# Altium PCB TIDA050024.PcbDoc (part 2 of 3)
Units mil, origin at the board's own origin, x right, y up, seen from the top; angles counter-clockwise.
Board outline 5500.19 x 3301.39 mil, 4 copper layers (Top Layer, Signal Layer 1, Signal Layer 2, Bottom Layer), stack 46.8 mil thick; 153 components, 88 nets, 368 pads, 374 vias.
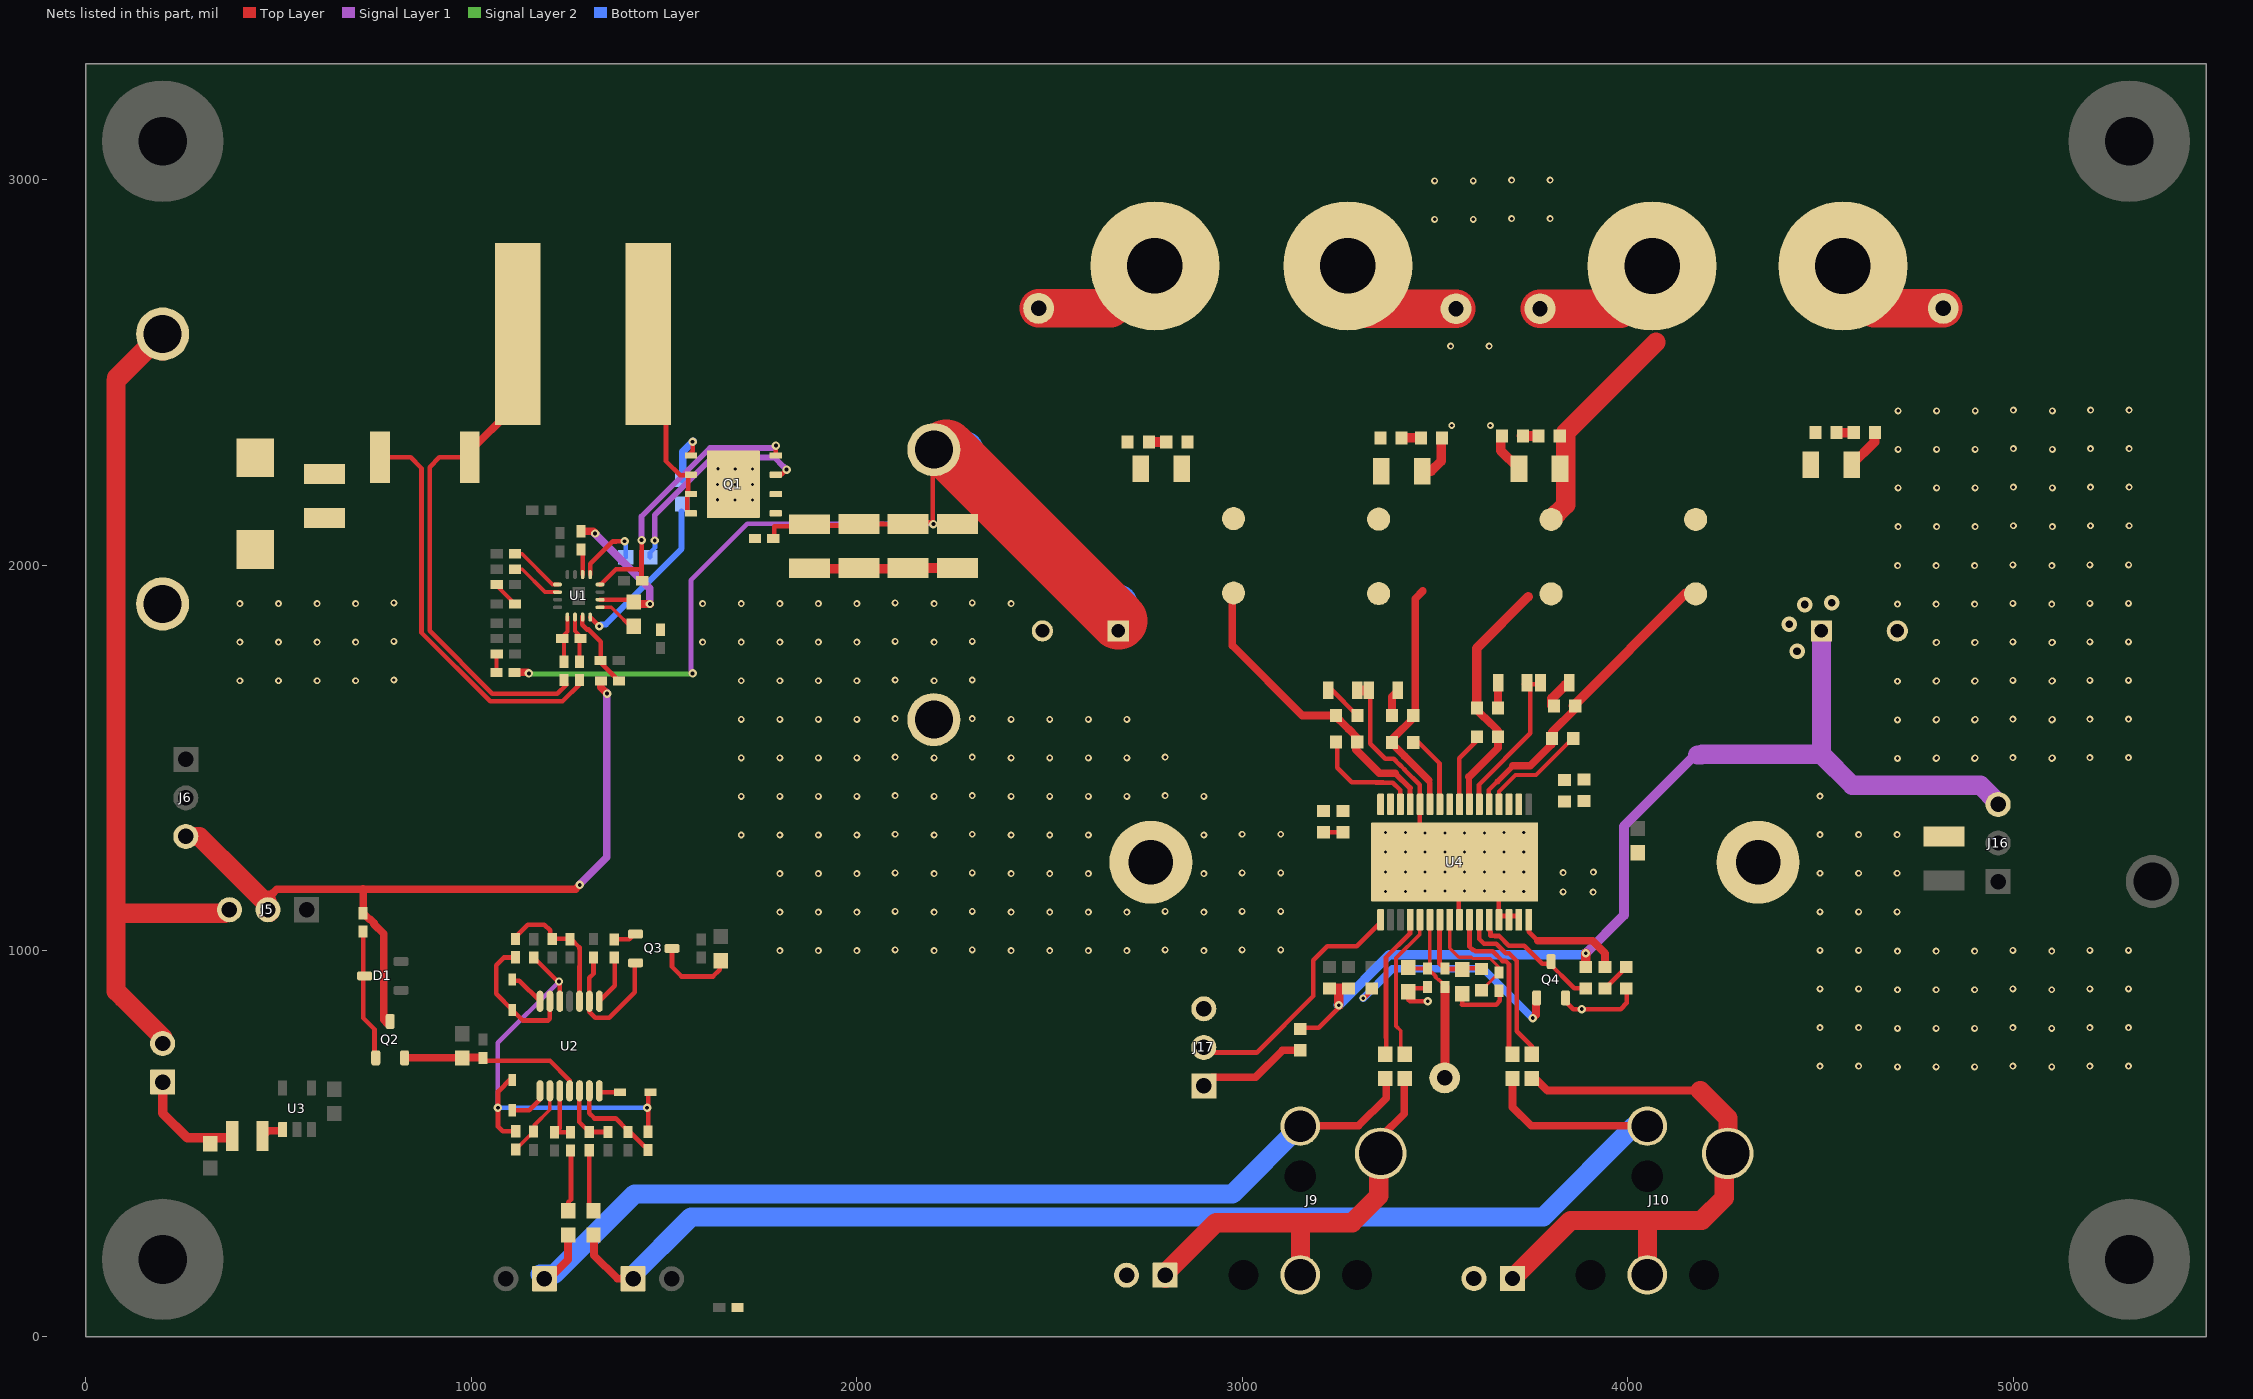
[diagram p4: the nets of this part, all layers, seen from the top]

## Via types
v1: diameter 18, hole 9, Top Layer to Bottom Layer, 291 vias
v2: diameter 22, hole 10, Top Layer to Bottom Layer, 26 vias
v3: diameter 19.68, hole 7.87, Top Layer to Bottom Layer, 18 vias
v4: diameter 19.68, hole 7.87, Top Layer to Bottom Layer, tented both sides, 16 vias
v5: diameter 18, hole 8, Top Layer to Bottom Layer, 9 vias
v6: diameter 40, hole 20, Top Layer to Bottom Layer, 6 vias
v7: diameter 24, hole 12, Top Layer to Bottom Layer, 5 vias
v8: diameter 20, hole 10, Top Layer to Bottom Layer, 2 vias
v9: diameter 30, hole 15, Top Layer to Bottom Layer, 1 vias

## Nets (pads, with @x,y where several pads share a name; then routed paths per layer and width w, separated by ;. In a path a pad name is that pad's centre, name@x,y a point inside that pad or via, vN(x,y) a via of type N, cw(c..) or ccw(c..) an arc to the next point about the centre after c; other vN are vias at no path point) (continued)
GND: C1.2 C2.2 C5.2 C6.2 C7.2 C8.2 C9.2 C17.2 C25.2 C27.2 C29.1 C30.1 C32.2 C39.2 C42.1 C43.1 C44.2 C46.2 C51.2 C53.2 C54.2 C55.1 C56.1 H1.1@4337.4,1230 H1.2 J2.1 J4.1 J17.3 JP1.2 JP2.2 Q1.9 Q4.2 R27.1@3480.57,906.95 R28.1 R33.1 R34.1 R35.1 R36.1 R39.1 R40.1 R41.1 R42.1 Rg1.2 Rg2.2 U1.9 U4.9 U4.13 U4.14 U4.15 U4.22 U4.25 U4.28 U4.33@3550.57,1230.57 | length 2518.7
  Top Layer w10: U1.9@1334.28,1891.31 1363.22,1891.31 C17.2@1425.03,1829.5
  Top Layer w12: J2.1@200,1950 J2.1@239.31,1950 ; C7.2@2000.71,1990.96 C7.2@2000.71,1998.84 ; C55.1@3210.57,1308.01 3259.88,1308.01 C56.1@3260.66,1308.79 ; R34.1@3314.8,1677.27 3331.52,1677.27 3331.52,1537.28 3370.58,1498.23 3392.56,1498.23 3406.22,1484.57 3406.35,1484.57 3420.41,1470.51 3420.41,1470.38 3460.18,1430.61 U4.28@3460.18,1389.88 ; U4.33@3460.16,1329.86 U4.28@3460.16,1386.09 ; R27.1@3479.4,903.4 3479.01,903.01 3430.57,903.01 3430.57,873.67 3434.63,869.61 v2(3480.67,869.61) ; U4.33@3481.22,1308.79 3482.72,1308.79 U4.33@3483.49,1309.56 ; U4.33@3536.23,1300.8 U4.33@3536.95,1301.52 ; U4.33@3561.5,1142.57 3561.5,1090.71 U4.9@3563.88,1088.33 ; 3569.63,860.55 3569.95,860.87 ; C43.1@3570.57,903.01 3570.57,861.48 3569.95,860.87 ; U4.22@3616.95,1362.32 3613.72,1362.32 3613.72,1431.43 3747.04,1564.75 R35.1@3747.04,1691.44 ; U4.33@3664.41,1144.48 3664.41,1091.16 3663.9,1090.66 U4.15@3716.08,1090.66 ; R28.1@3667.92,905.02 3667.92,870.86 3657.93,860.87 3569.95,860.87 ; R35.1@3729.76,1692.08 3761.32,1692.08 R36.1@3763.24,1694 ; Q4.2@3838.19,880.03 3838.19,874.94 3835.22,871.97 3857.99,849.2 v2(3880.17,849.2) ; v2(3880.17,849.2) 3980.83,849.24 3996.8,865.21 C46.2@3996.8,900.6 ; C27.2@4021.45,1260.32 C27.2@4024,1257.77
  Top Layer w25: C6.2@1872.99,1988.19 1875.76,1990.96 2000.71,1990.96 2122.16,1990.96 2126.31,1995.11 2128.33,1993.09 C9.2@2260.76,1993.09 ; R33.1@3298.17,1675.9 3298.49,1675.57 R34.1@3328.17,1675.57 ; C32.2@3466.58,2244.29 3489.62,2244.29 3515.78,2270.46 R40.1@3515.78,2327.98 ; R41.1@3673.15,2337.81 3669.93,2334.59 3669.93,2297.86 3717.21,2250.57 C39.2@3717.42,2250.57 ; C44.2@4580.3,2260.95 4639.42,2320.07 R42.1@4639.42,2345.02
  other v1: 4698.97,699.5 4798.97,699.5 4898.97,699.5 5098.97,699.5 4497.99,701.49 4597.99,701.49 4997.99,701.49 5197.99,701.49 5297.99,701.49 4698.97,799.5 4798.97,799.5 4898.97,799.5 5098.97,799.5 4497.99,801.49 4597.99,801.49 4997.99,801.49 5197.99,801.49 5297.99,801.49 4698.97,899.5 4798.97,899.5 4898.97,899.5 5098.97,899.5 4497.99,901.49 4597.99,901.49 4997.99,901.49 5197.99,901.49 5297.99,901.49 4698.97,999.5 4798.97,999.5 4898.97,999.5 5098.97,999.5 1800.45,1000.73 1900.45,1000.73 2000.45,1000.73 2200.45,1000.73 2400.45,1000.73 2500.45,1000.73 2600.45,1000.73 2700.45,1000.73 2900.45,1000.73 4497.99,1001.49 4597.99,1001.49 4997.99,1001.49 5197.99,1001.49 5297.99,1001.49 2099.47,1002.72 2299.47,1002.72 2799.47,1002.72 2999.47,1002.72 3099.47,1002.72 1800.45,1100.73 1900.45,1100.73 2000.45,1100.73 2200.45,1100.73 2400.45,1100.73 2500.45,1100.73 2600.45,1100.73 2700.45,1100.73 2900.45,1100.73 4497.99,1101.49 4597.99,1101.49 4697.99,1101.49 2099.47,1102.72 2299.47,1102.72 2799.47,1102.72 2999.47,1102.72 3099.47,1102.72 3832.05,1153.49 3909.58,1152.56 1800.45,1200.73 1900.45,1200.73 2000.45,1200.73 2200.45,1200.73 2400.45,1200.73 2500.45,1200.73 2600.45,1200.73 2900.45,1200.73 4497.99,1201.49 4597.99,1201.49 4697.99,1201.49 2099.47,1202.72 2299.47,1202.72 2999.47,1202.72 3099.47,1202.72 3831.95,1203.31 3910.53,1204.48 1700.45,1300.73 1800.45,1300.73 1900.45,1300.73 2000.45,1300.73 2200.45,1300.73 2400.45,1300.73 2500.45,1300.73 2600.45,1300.73 2900.45,1300.73 4497.99,1301.49 4597.99,1301.49 4697.99,1301.49 2099.47,1302.72 2299.47,1302.72 2999.47,1302.72 3099.47,1302.72 1700.45,1400.73 1800.45,1400.73 1900.45,1400.73 2000.45,1400.73 2200.45,1400.73 2400.45,1400.73 2500.45,1400.73 2600.45,1400.73 2700.45,1400.73 2900.45,1400.73 4497.99,1401.49 2099.47,1402.72 2299.47,1402.72 2799.47,1402.72 4698.97,1499.5 4798.97,1499.5 4898.97,1499.5 5098.97,1499.5 1700.45,1500.73 1800.45,1500.73 1900.45,1500.73 2000.45,1500.73 2200.45,1500.73 2400.45,1500.73 2500.45,1500.73 2600.45,1500.73 2700.45,1500.73 4800.45,1500.73 4900.45,1500.73 4997.99,1501.49 5100.45,1500.73 5197.99,1501.49 5297.99,1501.49 2099.47,1502.72 2299.47,1502.72 2799.47,1502.72 4698.97,1599.5 4798.97,1599.5 4898.97,1599.5 5098.97,1599.5 1700.45,1600.73 1800.45,1600.73 1900.45,1600.73 2000.45,1600.73 2400.45,1600.73 2500.45,1600.73 2600.45,1600.73 2700.45,1600.73 4800.57,1600.57 4900.57,1600.57 4997.99,1601.49 5100.57,1600.57 5197.99,1601.49 5297.99,1601.49 2099.47,1602.72 2299.47,1602.72 4698.97,1699.5 4798.97,1699.5 4898.97,1699.5 5098.97,1699.5 400.45,1700.73 500.45,1700.73 600.45,1700.73 700.45,1700.73 1700.45,1700.73 1800.45,1700.73 1900.45,1700.73 2000.45,1700.73 2200.45,1700.73 4800.45,1700.73 4900.45,1700.73 4997.99,1701.49 5100.45,1700.73 5197.99,1701.49 5297.99,1701.49 799.47,1702.72 2099.47,1702.72 2299.47,1702.72 4798.97,1799.5 4898.97,1799.5 5098.97,1799.5 400.45,1800.73 500.45,1800.73 600.45,1800.73 700.45,1800.73 1600.45,1800.73 1700.45,1800.73 1800.45,1800.73 1900.45,1800.73 2000.45,1800.73 2200.45,1800.73 4800.57,1800.57 4900.57,1800.57 4997.99,1801.49 5100.57,1800.57 5197.99,1801.49 5297.99,1801.49 799.47,1802.72 2099.47,1802.72 2299.47,1802.72 4698.97,1899.5 4798.97,1899.5 4898.97,1899.5 5098.97,1899.5 400.45,1900.73 500.45,1900.73 600.45,1900.73 700.45,1900.73 1600.45,1900.73 1700.45,1900.73 1800.45,1900.73 1900.45,1900.73 2000.45,1900.73 2200.45,1900.73 2400.45,1900.73 4997.99,1901.49 5197.99,1901.49 5297.99,1901.49 799.47,1902.72 2099.47,1902.72 2299.47,1902.72 4699.09,1999.34 4799.09,1999.34 4899.09,1999.34 5099.09,1999.34 4998.1,2001.33 5198.1,2001.33 5298.1,2001.33 4700.45,2100.73 4800.45,2100.73 4900.45,2100.73 5100.45,2100.73 4999.47,2102.72 5199.47,2102.72 5299.47,2102.72 4700.45,2200.73 4800.45,2200.73 4900.45,2200.73 5100.45,2200.73 4999.47,2202.72 5199.47,2202.72 5299.47,2202.72 4700.45,2300.73 4800.45,2300.73 4900.45,2300.73 5100.45,2300.73 4999.47,2302.72 5199.47,2302.72 5299.47,2302.72 3542.99,2362.72 3642.99,2362.72 4700.57,2400.57 4800.57,2400.57 4900.57,2400.57 5100.57,2400.57 4999.58,2402.56 5199.58,2402.56 5299.58,2402.56 3539.98,2568.29 3639.98,2568.29 3498.67,2897.45 3598.67,2897.45 3698.09,2899.06 3798.09,2899.06 3498.79,2997.3 3598.79,2997.3 3698.21,2998.9 3798.21,2998.9
  other v3: 3473.8,1155.77 3524.98,1155.77 3576.16,1155.77 3627.34,1155.77 3473.8,1204.98 3524.98,1204.98 3576.16,1204.98 3627.34,1204.98 3473.8,1256.16 3524.98,1256.16 3576.16,1256.16 3627.34,1256.16 3473.8,1305.37 3524.98,1305.37 3576.16,1305.37 3627.34,1305.37
  other v4: 3371.44,1153.8 3422.62,1153.8 3678.52,1153.8 3729.71,1153.8 3371.44,1204.98 3422.62,1204.98 3678.52,1204.98 3729.71,1204.98 3371.44,1256.16 3422.62,1256.16 3678.52,1256.16 3729.71,1256.16 3371.44,1307.34 3422.62,1307.34 3678.52,1307.34 3729.71,1307.34
  other v5: 1639.25,2170.19 1684.3,2169.73 1729.3,2169.73 1639.25,2210.19 1684.3,2209.73 1729.3,2209.73 1684.96,2250.16 1729.96,2250.16 1639.91,2250.62
GVDD: C43.2 R43.2 R44.1 U4.7 | length 236.8
  Top Layer w12: U4.7@3511.36,1090.66 3511.36,967.28 3525.23,953.4 3570.03,953.4 3572.28,955.65 R44.1@3618.04,955.65
HDRV: R11.1 U1.13 | length 195.3
  Top Layer w12: U1.13@1308.69,1975.96 1308.69,2004.49 1365.54,2061.34 1376.63,2061.34 ; 1367.02,2062.08 1370.35,2062.08 1370.72,2062.45 v2(1398.07,2062.45)
  Bottom Layer w12: v2@1397.94,2063.83 1400.87,2060.9 R11.1@1400.87,2021.02
HDRV1: Q1.3 R11.2 | length 560.2
  Top Layer w12: Q1.3@1790.04,2235 1804.57,2235 1818.06,2248.49 1818.06,2248.69 v2@1817.68,2249.08
  Signal Layer 1 w12: 1810.08,2256.03 1811.72,2256.03 1811.72,2253.98 v2@1810.49,2252.75
  Signal Layer 1 w15: v2(1476.07,2064.49) 1476.07,2130.41 1625.05,2279.38 1786.72,2279.38 1810.08,2256.03
  Bottom Layer w12: R11.2@1463.86,2021.02 1463.86,2032.96 1476.72,2045.82 v2@1476.72,2064.07 ; v2@1476.21,2064.58 v2@1476.21,2065.34
  other v2: 1818.25,2248.5
ISNS+: C10.2 R01.1 U1.6 | length 125.3
  Top Layer w10: U1.6@1269.32,1865.72 1269.52,1865.52 1269.52,1830.01 1286.72,1812.81 1280.56,1806.65 R01.1@1280.56,1750.22
ISNS-: C10.1 R02.1 U1.5 | length 117.9
  Top Layer w10: C10.1@1233.89,1814.22 1235.56,1814.22 1249.63,1828.29 U1.5@1249.63,1865.72 ; R02.1@1240.56,1750.22 1240.56,1805.72 C10.1@1242.94,1808.1
LDRV: R10.1 U1.8 | length 426
  Top Layer w12: U1.8@1308.69,1865.72 v2(1332.15,1842.26)
  Bottom Layer w12: v2(1332.15,1842.26) v2@1336.83,1846.95
  Bottom Layer w16: v2@1336.83,1846.95 1349.18,1846.95 1545.59,2043.36 1545.59,2139.47
LDRV1: Q1.5 R10.2 | length 149.2
  Top Layer w12: Q1.5@1566.26,2287.66 1574.77,2296.17 v2@1574.77,2321.63
  Bottom Layer w12: v2@1574.27,2318.94 v2(1574.27,2320.37)
  Bottom Layer w20: R10.2@1548.42,2222.91 1548.42,2294.52 v2@1575.81,2321.9
LIN: C21.1 C38.1 J8.1 J10.3 | length 3442.1
  Top Layer w20: C21.1@1318.41,261.7 1318.41,211.28 1379.68,150 J8.1@1420,150 J8.1@1410.01,159.99 ; C38.1@3700.49,668.52 3700.49,594.85 3748.94,546.4 J10.3@4050.57,546.4
  Bottom Layer w25: J8.1@1411.17,151.17 J8.1@1414.32,148.02
  Bottom Layer w50: J8.1@1411.17,151.17 1570,310 3780,310 4015.83,545.83 J10.3@4050,545.83
LINN: C41.2 U4.11 | length 431.7
  Top Layer w12: U4.11@3614.55,1080.97 3614.55,1030.95 3626.62,1018.88 3658.01,1018.88 3682.95,993.94 3691.47,993.94 3711.38,974.03 3711.38,934.11 3711.49,934 3711.49,791.8 3751.83,751.45 3748.25,747.87 C41.2@3748.25,731
LINP: C38.2 U4.10 | length 430.8
  Top Layer w12: U4.10@3588.96,1080.97 3588.96,1011.49 3598.7,1001.75 3601.7,1001.75 3604.57,998.88 3649.73,998.88 3674.67,973.94 3683.18,973.94 3691.38,965.74 3691.38,909.07 3691.49,908.96 C38.2@3691.49,725.88
MODSEL: J17.2 U4.1 | length 680
  Top Layer w12: J17.2@2900,750 2913.44,736.56 3036.8,736.56 3183.56,883.33 3183.56,975.73 ; 3183.65,975.64 3220.34,1012.34 3297.05,1012.34 3357.95,1073.24 3357.49,1073.7 U4.1@3357.49,1096.02
MUTE: Q4.3 R30.2 U4.12 | length 355.4
  Top Layer w12: U4.12@3640.14,1080.97 3640.14,1053.41 3643.37,1050.17 3643.37,1039.91 3653.64,1039.91 3654.67,1038.88 3666.3,1038.88 3691.24,1013.94 3730.91,1013.94 3777.6,967.26 Q4.3@3800.42,967.26 ; Q4.3@3800.42,970.84 Q4.3@3800.42,967.26 ; R30.2@3890.57,901.29 R30.2@3894,901.29 ; R30.2@3890.57,903.01 3861.12,903.01 3852.12,912.01 3852.07,912.01 3800.42,963.67 Q4.3@3800.42,967.26
NetC11_1: C11.1 R5.1 U1.7 | length 261.4
  Top Layer w10: U1.7@1288.7,1867.06 1288.7,1847.24 1302.13,1833.81 1303.13,1832.81 1303.93,1832.81 1310.37,1826.37
  Top Layer w12: U1.7@1288.11,1867.43 1288.11,1845.93 1300.23,1833.81 1302.13,1833.81 1304.34,1833.81 1311.37,1826.78 1311.37,1826.47 1335.72,1802.12 C11.1@1335.72,1752.85 ; C11.1@1335.94,1754.83 1335.94,1747.69 R5.1@1383.62,1700
NetC13_1: C13.1 R7.1 | length 70.2
  Top Layer w10: R7.1@1066.51,1949.49 1067.83,1948.17 1069.81,1948.17 1069.81,1943.81 C13.1@1113.62,1900
NetC15_1: C15.1 U1.2 | length 136.8
  Top Layer w10: C15.1@1113.62,1990 1132.52,1990 1191.47,1931.05 1224.65,1931.05 1225.37,1930.32 U1.2@1225.62,1930.57
NetC20_2: C20.2 R13.2 | length 161.4
  Top Layer w12: C20.2@1251.93,326.52 1251.93,348.52 1258.99,355.59 1258.99,484.51 R13.2@1259.3,484.82
NetC21_2: C21.2 R19.2 | length 160.5
  Top Layer w12: R19.2@1305.43,481.76 1305.43,481.15 1306.35,480.24 1306.35,337.11 C21.2@1317.29,326.17
NetC22_1: C22.1 R23.2 R24.2 U2.10 | length 359.8
  Top Layer w12: R23.2@1114.15,1034.64 1114.15,1035.59 1146.67,1068.11 1190.03,1068.11 1204.69,1053.45 1204.69,1031.13 1205.65,1032.09 1257.93,1032.09 1281.08,1008.94 1281.08,1006.39 1281.93,1005.54 1281.93,961.6 1281.08,960.75 U2.10@1281.08,869.61
NetC31_1: C31.1 J9.1 J9.4 JP1.1 | length 1121.1
  Top Layer w20: J9.4@3359.23,475.53 3359.23,517.63 3419.49,577.89 C31.1@3419.49,669.85
  Top Layer w50: JP1.1@2800.57,150.57 2800.57,164.61 2931.53,295.57 3285.07,295.57 3353.89,364.4 J9.4@3353.89,479.69 ; 3146.53,295.33 3150.57,291.29 J9.1@3150.57,160.57
NetC33_2: C33.2 R40.2 | length 47.8
  Top Layer w25: C33.2@3413.13,2330.57 3460.85,2330.57 R40.2@3460.92,2330.64
NetC34_2: C34.2 U4.26 | length 187
  Top Layer w12: C34.2@3443.13,1540.57 3456.95,1540.57 3511.36,1486.16 U4.26@3511.36,1389.88
NetC35_2: C35.2 U4.30 | length 281.5
  Top Layer w12: C35.2@3245.86,1542.3 3245.86,1475.55 3284.14,1437.27 3345.37,1437.27 3345.65,1436.99 3365.21,1436.99 3365.63,1436.57 3389.86,1436.57 3409,1417.44 U4.30@3409,1389.88
NetC36_2: C36.2 U4.24 | length 185.8
  Top Layer w12: U4.24@3562.54,1389.88 3562.54,1459.24 3562.37,1459.4 3562.37,1499.53 3605.21,1542.36 C36.2@3605.21,1557.89
NetC37_2: C37.2 U4.20 | length 274.1
  Top Layer w10: U4.20@3665.36,1389.48 3665.36,1413.65 3707.89,1456.18 3761.19,1456.18 3762.7,1457.69 3762.97,1457.69 3857.15,1551.87 C37.2@3857.15,1552.76
NetC40_2: C40.2 R41.2 | length 49.5
  Top Layer w25: R41.2@3727.93,2336.52 3723.42,2336.52 3724.37,2335.57 R41.2@3728.13,2335.57 C40.2@3768.01,2335.57
NetC41_1: C41.1 J10.1 J10.4 JP2.1 | length 1538.2
  Top Layer w20: C41.1@3755.91,673.42 3791.13,638.2 4187.38,638.2
  Top Layer w50: JP2.1@3700.57,150.57 3851.2,301.2 4190.98,301.2 4249.39,359.61 J10.4@4249.39,488.22 ; J10.1@4050.57,160.57 4050.57,293.35 4052.63,295.41 ; 4187.38,638.2 4259.23,566.35 J10.4@4259.23,475.53
NetC45_2: C45.2 R42.2 | length 44.2
  Top Layer w25: C45.2@4541.03,2344.34 4584.26,2344.34 R42.2@4584.93,2345.02
NetC46_1: C46.1 R29.1 | length 76.3
  Top Layer w12: R29.1@3942.14,903.96 3942.14,904.7 C46.1@3995.57,958.13
NetC47_1: C47.1 R33.2 | length 102.7
  Top Layer w12: R33.2@3223.66,1678.7 3230.01,1678.7 C47.1@3298.13,1610.57
NetC48_1: C48.1 R34.2 | length 71
  Top Layer w20: C48.1@3388.01,1610.57 3388.01,1659.51 R34.2@3403.61,1675.1
NetC49_1: C49.1 R35.2 | length 66.1
  Top Layer w20: R35.2@3660.02,1695.43 3663.13,1692.31 C49.1@3663.13,1630.57
NetC50_1: C50.1 R36.2 | length 68.8
  Top Layer w25: C50.1@3803.01,1635.57 3803.01,1655.16 R36.2@3837.83,1689.97
NetC52_2: C52.2 R39.2 | length 46.7
  Top Layer w25: R39.2@2757.56,2320 2802.13,2320 2803.32,2321.19 2803.12,2321.39 C52.2@2803.12,2321.59
NetD1_3: D1.3 Q2.1 R17.1 | length 348.7
  Top Layer w12: R17.1@720.03,1050.4 720.03,937.84 720.39,937.48 720.39,826.16 749.47,797.07 Q2.1@749.47,713.87
NetD2_1: D2.1 D4.1 R16.2 R18.2 R22.2 U2.12 | length 1208.3
  Top Layer w12: D2.1@1104.49,670.14 1069.77,635.42 1069.77,544.38 1081.81,532.34 R16.2@1115.71,532.34 ; R18.2@1162.44,983.15 v8@1226.16,919.43 ; U2.12@1230.24,869.33 v8@1230.24,915.35 ; v2(1456.37,593.34) v2@1458.79,590.91 ; R22.2@1459.04,531.05 v2@1459.04,590.91 ; v2@1459.04,593.34 1459.04,630.34 D4.1@1462.99,634.29
  Signal Layer 1 w12: v2(1069.32,593.34) 1069.32,761.99 v8@1226.53,919.2
  Bottom Layer w12: v2@1072.12,593.34 v2(1456.37,593.34)
  other v8: 1227.66,920.94
NetD2_2: D2.2 U2.1 | length 108.4
  Top Layer w12: D2.2@1106.87,586.89 1150.42,586.89 1178.78,615.25 1178.78,638.97 1179.31,638.44 U2.1@1179.31,638.18
NetD3_1: D3.1 R23.1 U2.13 | length 348
  Top Layer w12: R23.1@1113.43,982.94 1084.44,982.94 1064.74,963.23 1064.74,889.02 D3.1@1106.87,846.89 1134,819.76 1199.27,819.76 1203.42,823.9 U2.13@1203.42,871.73
NetD3_2: D3.2 U2.14 | length 96
  Top Layer w12: D3.2@1104.95,923.21 1125.12,923.21 U2.14@1178.72,869.61
NetD4_2: D4.2 U2.7 | length 58.2
  Top Layer w12: U2.7@1331.99,634.58 1332.26,634.86 U2.7@1332.26,637.33 1335.77,633.82 D4.2@1386.12,633.82
NetJ17_1: J17.1 R38.1 | length 281.6
  Top Layer w20: J17.1@2900,650 2922.49,672.49 3034.18,672.49 3104.33,742.64 R38.1@3143.23,742.64
NetL1_1: L1.1 R0.2 R02.2 | length 1342.4
  Top Layer w12: R0.2@981.14,2280 917.69,2280 892.31,2254.62 892.31,1830 1055.14,1667.17 1167.22,1667.17 1167.57,1666.82 1188.28,1666.82 1188.63,1667.17 1223.63,1667.17 1246.22,1689.77 1246.22,1692.61 R02.2@1239.46,1699.37
  Top Layer w20: R0.2@981.14,2280 1118.96,2417.81 L1.1@1118.96,2597.97
NetL2_2: L2.2 U3.1 | length 56.6
  Top Layer w20: L2.2@459.37,520 473.12,533.75 U3.1@510.32,533.75
NetQ3_1: Q3.1 R27.1@1371.04,1030.14 | length 58.4
  Top Layer w12: R27.1@1371.04,1030.14 1409.97,1030.14 Q3.1@1423.7,1043.87
NetQ3_2: Q3.2 R25.2 U2.9 | length 382.7
  Top Layer w12: U2.9@1306.67,869.61 1306.67,930.62 1317.22,941.17 R25.2@1317.22,980.21 ; U2.9@1306.71,867.14 1306.71,842.6 1322.09,827.22 1358.43,827.22 1371.11,839.9 1371.46,839.9 1424.48,892.92 Q3.2@1424.48,967.27 ; U2.9@1307.37,845.22 U2.9@1307.37,862.72
NetQ3_3: Q3.3 R26.1 | length 221.3
  Top Layer w12: Q3.3@1520.79,1006.62 1520.79,958.61 1545.46,933.94 1627.17,933.94 1644.7,951.47 R26.1@1644.7,983.38
NetQ4_1: Q4.1 R37.2 | length 619.8
  Top Layer w12: v1@3312.77,876.48 3314.04,876.48 R37.2@3340.57,903.01
  Top Layer w20: v2(3753.07,825.8) 3761.24,833.96 Q4.1@3761.24,879.17
  Bottom Layer w20: v1(3313.33,877.83) 3389.32,953.81 3625.06,953.81 v2(3753.07,825.8)
NetR1_1: R1.1 R2.2 | length 45.9
  Top Layer w10: R1.1@1065.39,1722.61 1065.39,1767.33 R2.2@1066.21,1768.15
NetR8_2: R8.2 U1.1 | length 144.7
  Top Layer w10: R8.2@1113.62,2030 1131.62,2030 1211.37,1950.25 U1.1@1225.3,1950.25
NetR13_1: R13.1 R14.2 U2.3 | length 161.3
  Top Layer w12: R14.2@1212.19,529.3 1212.83,529.94 R14.2@1215.81,529.94 R14.2@1219.16,529.94 ; R14.2@1218.52,529.3 R14.2@1219.16,529.94 ; U2.3@1229.42,638.83 1229.42,638.4 U2.3@1230.95,636.87 ; U2.3@1229.9,637.33 1229.9,540.68 R14.2@1219.16,529.94 ; R13.1@1257.9,529.94 R14.2@1219.16,529.94
NetR15_2: R15.2 R16.1 U2.2 | length 186.4
  Top Layer w10: R16.1@1115.71,485.1 1163.14,532.53 1164.03,532.53 1164.03,548.34 1203.82,588.12 U2.2@1203.82,634.5
NetR19_1: R19.1 R20.2 U2.5 | length 162.9
  Top Layer w12: U2.5@1280.55,633.89 1280.55,556.52 1306.62,530.44 R20.2@1355.33,530.44
NetR21_2: R21.2 R22.1 U2.6 | length 248.8
  Top Layer w12: U2.6@1306.74,635.83 1306.74,578.76 1319.82,565.69 1374.65,565.69 1405.58,534.77 1408.08,534.77 1433.23,509.62 1433.23,509.51 1441.43,501.31 1441.54,501.31 R22.1@1459.04,483.81
NetR27_2: R27.2@1371.04,982.89 U2.8 | length 126.5
  Top Layer w12: U2.8@1332.26,869.61 1372.23,909.58 R27.2@1372.23,979.55
NetR28_2: R28.2 R44.2 U4.8 | length 302.1
  Top Layer w8: U4.8@3537.78,1080.97 3537.78,1007.4 3561.43,983.75 3594.24,983.75 3597.12,980.88 3642.27,980.88 3664.12,959.04 3664.12,941.95 3619.06,896.9 R44.2@3617.66,896.9
NetR29_2: R29.2 U4.16 | length 301.6
  Top Layer w12: U4.16@3742.79,1094.7 3742.79,1049.55 3766.15,1026.2
  Top Layer w20: 3766.15,1026.2 3907.94,1026.2 3940.57,993.57 R29.2@3940.57,958.13
OUTL+: C39.1 C40.1 J13.1 L21.2 TP5.1 | length 961.6
  Top Layer w50: L21.2@3800.57,2119 3838.5,2156.93 3838.5,2344.56 4072.5,2578.56 ; J13.1@4069.38,2684.29 J13.1@4069.38,2751.28
  Top Layer w100: TP5.1@3771.82,2665.65 3980.4,2665.65 J13.1@4060.88,2746.13
OUTL-: C44.1 C45.1 J14.1 L22.2 TP7.1 | length 456.6
  Top Layer w50: J14.1@4465.95,2689.8 4542.61,2766.47 J14.1@4573.89,2766.47
  Top Layer w100: J14.1@4543.56,2764.98 4543.56,2761.36 4638.62,2666.3 TP7.1@4817.44,2666.3
OUTNL: C37.1 C50.2 L22.1 U4.21 | length 794.7
  Top Layer w12: U4.21@3639.31,1389.88 3639.31,1417.44 3661.4,1439.52
  Top Layer w15: 3661.4,1439.52 3701.88,1480
  Top Layer w20: 3701.88,1480 3746.51,1480 3801.52,1535.01 C37.1@3801.52,1553.2 ; C37.1@3803.01,1550.57 3803.01,1567.73 3862.83,1627.55 C50.2@3862.83,1633.44 ; C50.2@3858.13,1631.32 C50.2@3858.13,1635.57
  Top Layer w25: C50.2@3858.13,1635.57 4151.98,1929.42 L22.1@4162.59,1929.42
OUTNR: C34.1 C48.2 L12.1 U4.27 | length 608.2
  Top Layer w12: C34.1@3390.3,1535.86 C34.1@3390.3,1539.44 ; 3483.29,1437.29 3485.77,1434.81
  Top Layer w15: U4.27@3486.1,1389.8 3486.1,1434.74
  Top Layer w20: C34.1@3388.01,1540.57 3388.01,1548.69 C48.2@3446.81,1607.48 ; C34.1@3390.3,1535.86 3409.38,1516.78 3409.38,1516.38 3419.93,1505.84 3420.32,1505.84 3483.29,1442.87 ; C48.2@3443.13,1610.57 3448.09,1615.53 3448.09,1913.47 3468.07,1933.44
OUTPL: C36.1 C49.2 L21.1 U4.23 | length 639.4
  Top Layer w15: U4.23@3587.87,1384.8 3587.87,1451.84
  Top Layer w20: 3587.87,1451.84 3663.13,1527.1 C36.1@3663.13,1555.57 3663.13,1570.61 3629.66,1604.07 ; C49.2@3608.01,1630.57 3608.01,1624.99 3626.62,1606.38
  Top Layer w25: C49.2@3608.01,1630.57 3608.01,1785.49 3741.17,1918.64
OUTPR: C35.1 C47.2 L11.1 U4.29 | length 813.8
  Top Layer w12: 3384.57,1460.99 3388.05,1457.51 ; U4.29@3433.22,1391.24 3434.59,1389.88 3434.59,1422.4
  Top Layer w15: 3396.41,1460.57 3434.59,1422.4
  Top Layer w20: L11.1@2973.81,1916.21 2973.81,1792.34 3155.58,1610.57 C47.2@3243.01,1610.57 3243.01,1607.79 C47.2@3245.45,1605.35 ; C47.2@3244.64,1605.35 C47.2@3245.45,1605.35 ; C47.2@3246.81,1605.35 C47.2@3245.45,1605.35 ; C35.1@3295.58,1544.15 3294.66,1543.23 3294.66,1521.93 3355.6,1460.99 3384.57,1460.99 ; C35.1@3297.79,1542.04 3297.79,1553.21 3275.16,1575.84 3274.93,1575.84 3264.38,1586.38 C47.2@3245.45,1605.35 ; 3375.57,1460.57 3396.41,1460.57
OUTR+: C51.1 C52.1 J11.1 L11.2 TP2.1 | length 347.7
  Top Layer w100: TP2.1@2471.45,2666.3 2659.06,2666.3 2769.65,2776.89 J11.1@2773.39,2776.89
OUTR-: C32.1 C33.1 J12.1 L12.2 TP3.1 | length 364.4
  Top Layer w100: J12.1@3262.43,2748.59 3262.43,2682.94 3279.73,2665.65 3350.35,2665.65 TP3.1@3554.07,2665.65
PGOOD: R9.2 U1.14 | length 49.9
  Top Layer w12: U1.14@1289,1975.96 R9.2@1289,2025.82
PLIMIT: C42.2 R27.2@3480.57,954.19 R43.1 TP6.1 U4.6 | length 499
  Top Layer w10: C42.2@3430.57,958.13 3428.56,956.12 3428.56,955.33 3429.7,954.19 R27.2@3480.57,954.19 ; U4.6@3485.77,1090.66 3485.77,955.18 3483.02,952.43 3500.76,934.69 3500.76,932.7 3508.02,925.45 3510.01,925.45 3525.88,909.57 R43.1@3525.88,907.32
  Top Layer w23: TP6.1@3525.57,668.47 R43.1@3525.57,906.95
  Top Layer w25: TP6.1@3524.86,667.76 TP6.1@3525.57,668.47
PVCC: C5.1 C6.1 C7.1 C8.1 C9.1 C29.2 C30.2 C53.1 C54.1 C55.2 C56.2 J3.1 J16.3 Q1.1 Q1.2 R1.2 R30.1 R31.2 R32.1 R38.2 U4.18 U4.19 U4.31 U4.32 | length 5582
  Top Layer w12: C5.1@1784.48,2069.03 1786.34,2070.89 1786.34,2101.32 1877.53,2101.32 1879.58,2103.38 2002.86,2103.38 2004.04,2102.2 C7.1@2008.88,2107.05 ; C7.1@2005.85,2107.05 C7.1@2008.88,2107.05 ; 2069.91,2107.24 2009.07,2107.24 C7.1@2008.88,2107.05 ; J3.1@2198.98,2294.8 2196.9,2292.73 2196.9,2112.01 2133.73,2112.01 2128.77,2107.05 C7.1@2008.88,2107.05 ; R38.2@3142.24,800.95 3198.17,800.95 3250.1,852.89 v2(3250.1,859.29)
  Top Layer w20: R1.2@1112.63,1722.61 v2@1146.76,1722.61
  Top Layer w25: R31.2@3231.37,904.23 3232.59,903.01 R32.1@3275.57,903.01 ; 3249.8,897.77 3249.8,859.59 v2(3250.1,859.29) ; v2(3890.5,993.96) 3890.5,962.55 R30.1@3891.16,961.9
  Top Layer w100: J3.1@2198.3,2302.64 J3.1@2232.25,2302.64
  Top Layer w150: J3.1@2232.25,2302.64 C53.1@2678.43,1856.46
  Signal Layer 1 w12: v2(1574.25,1719.67) 1570,1723.92 1570,1961.44 1716.1,2107.54 v2@2196.56,2107.54
  Signal Layer 1 w25: v2(3890.5,993.96) 3989.56,1093.01 3989.56,1323.75 4171.47,1505.67 4179.83,1505.67
  Signal Layer 1 w50: 4180.43,1508.03 4190.38,1508.03 4192.17,1509.83 4501.57,1509.83 ; C54.1@4501.57,1830 4501.57,1509.83 ; J16.3@4958.56,1385.17 4914.08,1429.64 4581.77,1429.64 4501.57,1509.83
  Signal Layer 2 w12: v2@1149.21,1721.63 1152.47,1718.38 1572.96,1718.38 v2(1574.25,1719.67)
  Bottom Layer w25: v2@3249.38,860.02 v2(3250.1,859.29) 3380.61,989.8 3886.92,989.8 v2@3891.33,994.21
  Bottom Layer w100: J3.1@2197.2,2299 2279.28,2299 ; 2678.43,1890.08 2678.43,1899.86
  other v2: 1150,1720 2198.87,2106.87
  other v6: 4438.45,1777.29 4418.45,1847.29 4458.37,1898.28 4528.68,1902.89
RIN: C20.1 C26.1 J7.1 J9.3 | length 2579.5
  Top Layer w20: J7.1@1190,150 1201.82,150 1251.31,199.49 C20.1@1251.31,262.52 ; J9.3@3150.57,546.4 3300.98,546.4 3372.81,618.23 3372.81,666.58 C26.1@3369.54,669.85
  Bottom Layer w50: J7.1@1179.52,161.35 1214.75,161.35 1423.4,370 2974.17,370 J9.3@3150,545.83
RINN: C31.2 U4.5 | length 383.1
  Top Layer w10: C31.2@3420.57,742.07 3410.87,751.77 3410.87,793.2 3398.7,805.37 3398.7,866.49 3398.87,866.66 3398.87,982.14 3460.18,1043.44 U4.5@3460.18,1090.66
RINP: C26.2 U4.4 | length 371
  Top Layer w12: C26.2@3372.27,747.01 3372.87,747.61 3372.87,775.31 3372.57,775.61 3372.57,983.18 3434.59,1045.19 U4.4@3434.59,1090.66 ; C26.2@3372.82,747.56 C26.2@3372.82,748.85
SW: L1.2 Q1.6 Q1.7 Q1.8 | length 519.9
  Top Layer w12: L1.2@1459.29,2600 1505.3,2554 1505.3,2270.24 1541.77,2233.76 1562.25,2233.76 1562.82,2234.33 1562.82,2194.87 1560.53,2192.58 1560.53,2141.67 1563.39,2138.81 Q1.8@1563.39,2138.24
SW1: C16.1 Q1.4 U1.12 | length 794.8
  Top Layer w12: U1.12@1334.28,1950.37 1335.86,1950.37 1375.7,1990.2 1439.91,1990.2 1440.22,1989.9 ; C16.1@1441.72,1970.06 1441.72,2037.75 ; C16.1@1441.97,1962.8 v2(1441.97,2065.45) ; v2@1789.72,2309.63 1790.04,2309.31 Q1.4@1790.04,2285
  Signal Layer 1 w15: v2(1441.97,2065.45) 1441.97,2126.94 1619.13,2304.1 1782.81,2304.1 v2@1783.85,2305.14
  other v2: 1790.5,2310.8
V+: C18.1 C19.1 Q2.2 U2.4 | length 468.1
  Top Layer w12: C19.1@1038.96,715.23 1204.58,715.23 1254.95,664.86 U2.4@1254.95,638.67 ; U2.4@1255.35,637.7 U2.4@1256.97,637.7
  Top Layer w20: Q2.2@827.4,722.76 980.94,722.76 981.97,723.79 C19.1@1030.4,723.79
VCC: C17.1 R9.1 U1.10 | length 618.6
  Top Layer w12: U1.10@1334.28,1911 1423.43,1911 C17.1@1434.59,1899.84
  Top Layer w20: R9.1@1285,2088.62 1316.97,2088.62 v2@1320.06,2085.53 ; C17.1@1434.59,1899.84 1464.19,1899.84 1464.33,1899.69 v2@1464.77,1899.69
  Signal Layer 1 w12: v2@1319.67,2082.98 1320.02,2082.64 1320.67,2082.64 v2(1321.4,2082.64)
  Signal Layer 1 w20: v2@1319.67,2082.98 1319.83,2082.98 1463.41,1939.4 1463.41,1939.9 1320.67,2082.64 v2@1319.89,2083.43 ; v2(1463.41,1899.79) 1463.41,1938.28
VIN: C1.1 C2.1 J1.1 J5.3 JP3.2 R0.1 R01.2 | length 3496.9
  Top Layer w12: R0.1@748.86,2280 843.28,2280 871.24,2252.04 871.24,1825.62 1049.67,1647.18 1236.83,1647.18 R01.2@1281.37,1691.72 ; R01.2@1280.24,1699.26 R01.2@1280.61,1698.89
  Top Layer w20: 85.61,868.74 86.96,867.38 ; JP3.2@200,750 JP3.2@200,752.09
  Top Layer w50: 78.74,1108.44 78.74,2478.74 ; J1.1@197.49,2605.8 197.49,2603.57 80.45,2486.53 80.45,2480.45 J1.1@200,2600 J1.1@200,2555.66 ; JP3.2@201.1,774.68 80.03,895.76 79.17,895.76 79.17,1097.47 361.86,1097.47 J5.3@372.83,1108.44
Vin_ctrl: J5.2 J6.3 Q2.3 R5.2 R17.2 | length 2126.7
  Top Layer w20: J5.2@473.18,1106.94 473.18,1146.53 482.27,1146.53 495.91,1160.16 720.03,1160.16 ; 719.32,1161.09 720.03,1160.38 720.03,1160.16 ; Q2.3@783.21,812.04 773.06,822.2 773.06,1044.62 747.84,1069.83 747.84,1072.78 738.47,1082.15 735.52,1082.15 R17.2@720.03,1097.64 720.03,1160.16 ; v2(1281.68,1171.4) 1270.44,1160.16 720.03,1160.16 ; R5.2@1336.21,1696.98 1336.21,1683.8 v2(1352.47,1667.53)
  Top Layer w50: J6.3@260.09,1297.08 295.2,1297.08 404.18,1188.09 J5.2@470.39,1121.88 ; J5.2@470.39,1128.73 J5.2@470.39,1121.88 ; J5.2@471.21,1109.28 471.21,1121.06 J5.2@470.39,1121.88 ; J5.2@476.29,1099.89 470.39,1105.78 J5.2@470.39,1121.88
  Signal Layer 1 w20: v2(1281.68,1171.4) 1281.68,1172.78 1351.91,1243.01 v2@1351.91,1670.16
"Vin_one cell": C3.1 JP3.1 L2.1 | length 293.8
  Top Layer w25: JP3.1@200,670 200,579.15 263.42,515.72 374.17,515.72 L2.1@375.93,517.48
pads on no net: D1.2 H1.1@200,3100 H2.1 H3.1 H4.1 J9.M1 J9.M2 J9.M3 J10.M1 J10.M2 J10.M3 U4.33@3550.57,1230.57

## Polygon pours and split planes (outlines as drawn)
AGND on Top Layer "AGND_L01_P112" (solid, remove dead copper, pour order 112): 1376.75,1765.24 1391.48,1765.17 1428.4,1802.09 1540,1802.09 1540,1735.81 1389.47,1735.81 1376.73,1748.55
AGND on Top Layer "AGND_L01_P098" (solid, remove dead copper, pour order 98): 60,454.8 487.01,454.83 540.02,507.84 540.02,598.61 759.99,598.61 760.02,50 400,50 400,377.67 60,377.67
"Vin_one cell" on Top Layer "VIN_ONE_CELL_L01_P096" (solid, remove dead copper, pour order 96): 60.04,689.72 233.78,689.73 340.06,583.45 364.85,558.66 364.85,481.38 59.86,481.38
VIN on Top Layer "VIN_L01_P094" (solid, remove dead copper, pour order 94): 80.62,1219.53 190.95,1219.52 271.39,1139.08 390.5,1139.08 390.5,758.2 363.42,731.11 54.31,731.11 54.31,1193.21
AGND on Top Layer "AGND_L01_P062" (solid, remove dead copper, pour order 62): 1200,1990.03 1135.15,2055.04 1084.94,2055.04 1079.95,2050.05 1080.51,2049.49 1080.51,1980.67 1051.89,1980.67 1040.85,1969.64 1040.85,1933.08 1077.04,1896.9 1077.04,1798.06 917.26,1798.06 917.26,2104.32 1194.65,2104.32 1194.97,2065.12 1288.09,1972 1288.09,1922.35 1220.42,1990.03
OUTL- on Top Layer "Top Layer-No Net 16" (solid, remove dead copper, pour order 36): 4015.57,2055.57 4015.57,2180.57 4080.57,2180.57 4400.57,2500.57 4411.51,2511.51 4411.51,2677.38 4411.51,2701.26 4517.74,2807.5 4530.92,2820.67 4633.09,2820.67 4712.36,2737.79 4712.36,2587.36 4645.57,2520.57 4500.57,2375.57 4500.57,2055.57
OUTL+ on Top Layer "Top Layer-No Net 15" (solid, remove dead copper, pour order 34): 3640.57,2055.57 3640.57,2185.57 3775.57,2185.57 3795.57,2205.57 3800.61,2211.01 3800.57,2305.57 3805.57,2310.57 3805.57,2390.57 3915.57,2500.57 3915.57,2635.57 3915.57,2710.84 3984.05,2779.31 3990.31,2785.57 4190.57,2785.57 4190.57,2550.57 3960.57,2320.57 3960.57,2125.57 3960.57,2055.57
OUTR- on Top Layer "Top Layer-No Net 14" (solid, remove dead copper, pour order 32): 3190.57,2055.57 3190.57,2487.29 3120.57,2557.29 3119.19,2555.9 3120.57,2557.29 3120.57,2730.57 3205.57,2815.57 3360.57,2815.57 3362.24,2815.57 3432.6,2745.21 3435.57,2742.24 3435.57,2685.57 3435.57,2450.57 3380.57,2395.57 3380.57,2185.57 3455.57,2185.57 3515.57,2125.57 3515.57,2085.57 3515.57,2055.57
OUTR+ on Top Layer "Top Layer-No Net 13" (solid, remove dead copper, pour order 30): 2815.57,2055.57 2815.57,2180.57 2821.93,2186.93 2821.9,2261.9 2830.23,2270.23 2830.23,2425.91 2810.57,2445.57 2645.09,2611.06 2645.09,2763.15 2878,2763.15 2940.87,2700.29 2940.57,2525.57 2940.57,2320.57 3050.57,2210.57 3135.57,2125.57 3135.57,2055.57
OUTNL on Top Layer "Top Layer-No Net 12" (solid, remove dead copper, pour order 28): 3695.75,1485.57 3705.57,1485.57 3785.57,1565.57 3790.57,1570.57 3845.57,1625.57 3845.57,1645.87 3890.56,1690.86 3890.56,1720.56 4015.57,1845.57 4015.57,1990.57 4335.57,1990.57 4335.57,1910.57 4335.57,1905.57 4280.57,1850.57 4110.57,1680.57 4065.57,1680.57 4015.57,1680.57 3914.48,1579.48 3843.93,1579.48 3820.57,1556.12 3820.57,1530.57 3820.57,1525.57 3762.87,1467.87 3680.63,1467.87 3680.63,1470.46
PVCC on Top Layer "Top Layer-No Net 7" (solid, remove dead copper, pour order 18): 2707.36,1945.27 3229.27,1423.79 3377.35,1423.79 3390.57,1410.57 3390.57,1366.57 3384.57,1360.57 3110.57,1360.57 3052.48,1360.57 2851.23,1561.82 2587.57,1825.48
OUTPR on Top Layer "Top Layer-No Net 9" (solid, pour order 22): 2815.71,1990.24 2816.04,1990.57 3140.57,1990.57 3140.57,1670.57 3175.57,1635.57 3180.57,1630.57 3240.57,1630.57 3255.57,1630.57 3260.57,1625.57 3260.57,1590.57 3255.59,1585.59 3150.48,1585.59 3100.59,1585.59 3100.57,1585.57 3095.57,1585.57 2815.57,1865.57 2815.72,1865.72 2815.72,1990.24 2815.72,1990.26 2816.03,1990.56
OUTNR on Top Layer "Top Layer-No Net 10" (solid, remove dead copper, pour order 24): 3190.57,1990.57 3515.57,1990.57 3515.57,1595.57 3425.57,1595.57 3425.57,1630.57 3435.57,1640.57 3435.57,1660.57 3435.57,1690.57 3320.57,1805.57 3190.57,1805.57
OUTPL on Top Layer "Top Layer-No Net 11" (solid, remove dead copper, pour order 26): 3965.46,1990.78 3640.78,1990.78 3640.57,1860.57 3580.57,1800.57 3580.57,1610.57 3590.57,1600.57 3625.57,1600.57 3625.57,1716.24 3714.69,1805.36 3845.14,1805.36 3965.57,1925.57
OUTPL on Top Layer "Top Layer-No Net 8" (solid, remove dead copper, pour order 46): 3678.57,1543.57 3678.48,1529.09 3678.48,1527.17 3595.88,1444.57 3593.57,1442.26 3593.57,1386.55 3582.82,1386.55 3580.13,1383.86 3580.51,1384.24 3580.51,1457.24 3580.51,1477.63 3646.98,1544.1 3646.98,1551.38 3648.13,1552.53 3657.09,1543.57
OUTPR on Top Layer "Top Layer-No Net 19" (solid, remove dead copper, pour order 48): 3313.6,1530.53 3313.63,1523.11 3313.63,1520.57 3321.18,1513.02 3361.24,1472.96 3397.99,1472.96 3443.73,1427.26 3443.73,1388.38 3426.99,1388.38 3426.84,1415.78 3426.84,1418.45 3394.7,1450.59 3309.9,1450.59 3282.12,1478.15 3282.12,1530.13 3313.2,1530.13
OUTNR on Top Layer "Top Layer-No Net 20" (solid, remove dead copper, pour order 50): 3403.15,1543.23 3403.15,1536.81 3426.57,1513.38 3434.38,1505.58 3462.92,1505.58 3494.67,1473.82 3494.67,1391.5 3478.62,1391.5 3478.19,1391.94 3478.19,1433.14 3387.76,1524.01 3373.66,1523.79 3373.66,1542.88 3374.09,1543.31
VIN on Top Layer "VIN_L01_P070" (solid, remove dead copper, pour order 70): 100,2900 400,2900 786.13,2900 786.13,2210 100,2210
NetL1_1 on Top Layer "NETL1_1_L01_P072" (solid, remove dead copper, pour order 72): 1200,2900 1200,2230 1170,2200 965.68,2200 965.68,2900
SW on Top Layer "SW_L01_P074" (solid, remove dead copper, pour order 74): 1380,2836.77 1520,2836.77 1520,2298.93 1547.92,2271.01 1568.99,2271.01 1590,2250 1590,2130 1466.91,2130 1380,2216.91
PVCC on Top Layer "PVCC_L01_P080" (solid, remove dead copper, pour order 80): 1820,2200 1850,2230 1850,2512 2398.52,2512 2398.52,2060 1820,2060 1810,2050 1770,2050 1770,2190 1780,2200
AGND on Top Layer "AGND_L01_P082" (solid, remove dead copper, pour order 82): 740,50 1640.91,50 1640.91,1139.14 740,1139.14
GND on Top Layer "GND_L01_P086" (solid, remove dead copper, pour order 86): 910,2160 930,2140 930,1790 950,1770 1010,1770 1030,1750 1030,1660 1050,1640 1388.99,1640 1388.99,1836.26 1480,1927.27 1480,2070 1510,2100 1590,2100 1610,2120 1610,2400 1750,2400 1750,2050 1760,2040 2338.27,2040 2798.27,1580 2800,1580 2800,50 1700,50 1700,1050 1650,1100 1580,1100 1450,1230 138.09,1230 138.09,2160
PVCC on Top Layer "PVCC_L01_P088" (solid, remove dead copper, pour order 88): 3724.16,1354 3724.54,1409.53 3733.37,1418.37 3773.08,1418.24 3781.57,1426.73 4198.82,1426.73 4198.82,1427.41 4593.47,1822.06 4593.47,1888 4518.55,1962.91 4403.61,1962.91 4113.37,1672.67 4030.75,1672.67 3878.7,1520.63 3847.63,1520.56 3771.97,1445.2 3769.42,1442.57 3716.72,1442.68 3683,1408.96 3683,1354
GND on Top Layer "GND_L01_P090" (solid, remove dead copper, pour order 90): 1850,3238.85 5100,3238.85 5100,2900 5400,2900 5400,400 5100,400 5100,51.51 1850,51.51
5V on Top Layer "5V_L01_P106" (solid, remove dead copper, pour order 106): 540,1140 660,1140 660,636.16 653.84,630 574.24,630 574.24,663.67 599.76,689.18 599.76,1010.24 540,1070
GND on Top Layer "GND_L01_P110" (solid, remove dead copper, pour order 110): 1342.58,1897.07 1371.26,1897.07 1392.81,1875.51 1442.9,1875.51 1442.9,1814.86 1442.47,1814.43 1395.61,1814.43 1395.61,1818.16 1322.14,1891.63 1322.14,1896.76
AGND on Signal Layer 1 "AGND_L02_P114" (solid, remove dead copper, pour order 114): 60,1580 480,1580 480,380 60,380
GND on Signal Layer 1 "GND_L02_P100" (solid, remove dead copper, pour order 100): 72.47,1620 643.39,1620 643.39,2073.39 770,2200 1623.79,2200 1623.79,50 5100,50 5100,400 5400,400 5400,2900 5100,2900 5100,3200 400,3200 400,2900 72.47,2900
AGND on Signal Layer 1 "AGND_L02_P068" (solid, remove dead copper, pour order 68): 390,1691.34 810,2110 1276.98,2110 1277.39,2109.59 1489.9,2109.59 1591.91,2007.58 1591.91,50 390,50
AGND on Signal Layer 1 "AGND_L02_P060" (solid, remove dead copper, pour order 60): 1000.32,2090.54 1020,2110.22 1350.01,2110.22 1476.24,1983.43 1476.24,1812.41 1413.91,1750.08 1050.26,1750.12 1000,1800.37 1000,2090 1020,2110
GND on Signal Layer 2 "GND_L03_P084" (solid, remove dead copper, pour order 84): 400,3200 5100,3200 5100,2900 5400,2900 5400,400 5100,400 5100,100 400,100 400,399.07 399.07,400 100,400 100,2900 400,2900
GND on Bottom Layer "GND_L04_P116" (solid, remove dead copper, pour order 116): 100,2800 500,2800 500,3200 5000,3200 5000,2800 5400,2800 5400,500 5000,500 5000,100 500,100 500,500 100,500
GND on Bottom Layer "GND_L04_P104" (solid, remove dead copper, pour order 104): 1590.26,2099.89 1749.74,2099.89 1749.74,2293.04 1739.85,2302.93 1739.85,2303.14 1657.37,2303.14 1657.16,2303.35 1590.24,2236.43 1590.24,2099.95
PVCC on Bottom Layer "PVCC_L04_P092" (solid, remove dead copper, pour order 92): 2184.33,2420 2534.44,2420 2833.1,2121.34 4476.15,2121.34 4605.52,1991.96 4605.52,1797.03 4554.03,1745.53 2654.96,1745.53 2129.01,2271.49 2129.01,2364.68 2167.89,2403.59

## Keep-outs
Keep-Out Layer:
  text ".Layer_Name" at 577,-858.49 h30

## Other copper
Top Layer:
  pour cut-out: 2517.35,1861.19 2573.09,1861.19 3075.47,1358.81 3047.6,1330.94
  pour cut-out: 3055.57,1352.38 3182.57,1352.57 3182.55,1335.67 3055.58,1335.66
  pour cut-out: 4418.69,2049.19 4507.06,2137.56 4507.06,2049.19
  pour cut-out: 3475.65,1595.57 3515.57,1635.5 3515.57,1595.57
  text ".Layer_Name" at 577,-858.49 h30
Bottom Layer:
  text ".Layer_Name" at 577,-858.49 h30

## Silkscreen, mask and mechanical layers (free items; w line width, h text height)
Top Overlay:
  circle w15: c1153.13,590.01 r7
  circle w15: c3314.77,1070.45 r7
  text "OUTL-" at 4464.76,3040.16 h50
  text "OUTL+" at 3944.75,3037.75 h50
  text "OUTR+" at 2648.59,3034.19 h50
  text "OUTR-" at 3147.99,3034.19 h50
  text "TIDA-050024" at 1582.69,2960.43 h70
  text "VIN" at 133.42,2727.25 h50
  text "VOUT" at 2128.36,2448.03 h30
  text "GND" at 132.71,1714.73 h50
  text "OFF" at 346.95,1468.26 h40
  text "GND" at 2160,1450 h30
  text "EN" at 349.02,1371.61 h40
  text "PVCC" at 5047.76,1363.06 h30
  text "ON" at 349.71,1268.06 h40
  text "AVCC" at 5043.16,1259.89 h30
  text "AVCC_IN" at 5042.24,1153.03 h30
  text "OneCell" at 459.07,857.89 h35 r45
  text "Vin_Ctrl" at 334.07,855.9 h35 r45
  text "TwoCell" at 224.97,854.28 h35 r45
  text "LOW" at 2699.12,830.98 h30
  text "VIN" at 274.61,735.21 h35
  text "MOD" at 2699.75,730.94 h30
  text "5V_GEN" at 275.42,633.59 h35
  text "HIGH" at 2698.49,629.65 h30
  text "RI" at 2812.09,350.16 h50
  text "LI" at 3722.43,335.6 h50
  text "RIN" at 1158.06,43.63 h30
  text "LIN" at 1367.63,44.43 h30
  text "GND" at 1020.54,31.18 h30
  text "GND" at 1473.42,30.16 h30
  text ".Layer_Name" at 577,-858.49 h30
Bottom Overlay:
  text ".Layer_Name" at 577,-858.49 h30
Top Paste:
  text ".Layer_Name" at 577,-858.49 h30
Bottom Paste:
  text ".Layer_Name" at 577,-858.49 h30
Top Solder:
  text ".Layer_Name" at 577,-858.49 h30
  text ".Layer_Name" at 577,-858.49 h30
Bottom Solder:
  text ".Layer_Name" at 577,-858.49 h30
Drill Guide:
  text ".Layer_Name" at 577,-858.49 h30
M1 Board Outline:
  lines w10: 0,0 5500,0 ; 0,0 0.57,0.57 0.57,3301.39 ; 0,0 5500,0 ; 0,0 0.57,3301.39 ; 0.57,3301.39 5500.19,3301.39 ; 0.57,3301.39 5500.19,3301.39 ; 5500,0 5500.19,0.19 ; 5500,0 5500.19,0.19 ; 5500.19,0.19 5500.19,3301.39 ; 5500.19,0.19 5500.19,3301.39
  text ".Layer_Name" at 577,-858.49 h30
M2 Board Dimensions:
  rectangle: 125,-400 500,-275
  rectangle: 0,-275 125,-150
  lines w7: 0,-275 1000,-275 ; 125,-400 125,-150 ; 250,-400 250,-150 ; 500,-400 500,-150 ; 750,-400 750,-150 ; 0,-400 0,-150 1000,-150 1000,-400 0,-400
  text ".Layer_Name" at 577,-858.49 h30
M3 3D STEP Top:
  text ".Layer_Name" at 577,-858.49 h30
M4 3D STEP Bottom:
  text ".Layer_Name" at 577,-858.49 h30
M5 Assembly Top:
  lines w10: -292,-930.17 6308,-930.17 ; -292,-726.83 6310,-726.83 ; -292,-523.5 -292,-1133.5 3713,-1133.5 6310,-1133.5 6310,-523.5 -291.5,-523.5 -291.5,-1133.5 1284,-1133.5 ; 2173,-1133.5 2173,-523.5 ; 3440,-726.83 3440,-523.5 ; 4280,-726.83 4280,-523.5 ; 4902,-1140 4902,-937.17
  text "COMPONENTS MARKED 'DNP' SHOULD NOT BE POPULATED." at 1153.5,-318.5 h30
  text "ASSEMBLY VARIANT:" at 1153,-434 h30
  text ".VariantName" at 2489,-434 h30
  text "PCB VIEWED FROM TOP SIDE" at -228.5,-655.67 h30
  text "BOARD #:" at 2248,-655.67 h30
  text ".PRJ_Number" at 2793.5,-655.67 h30
  text "REV:" at 3638,-655.67 h30
  text ".PCB_Rev" at 3929.5,-655.67 h30
  text "SVN REV:" at 4476,-655.67 h30
  text ".VersionControl_RevNumber" at 4982,-655.67 h30
  text "TID #:" at 2248,-859 h30
  text ".TID" at 2793.5,-859 h30
  text "PLOT NAME =" at -228.5,-1064.34 h30
  text ".plot_File_Name" at 577,-1064.34 h30
  text "GENERATED    :" at 2250,-1064.34 h30
  text ".Print_Date" at 3119.5,-1064.34 h30
  text ".Print_Time" at 3848.5,-1064.34 h30
  text "TEXAS INSTRUMENTS" at 5113,-1064.34 h30
M6 Assembly Bottom:
  lines w10: -292.5,-727.33 6309.5,-727.33 ; -290.5,-930.67 6309.5,-930.67 ; 1115.5,-1140.5 1115.5,-937.67 ; 1737.5,-727.33 1737.5,-524 ; 2577.5,-727.33 2577.5,-524 ; 3844.5,-1134 3844.5,-524 ; 4733.5,-1134 6309,-1134 6309,-524 -292.5,-524 -292.5,-1134 2304.5,-1134 6309.5,-1134 6309.5,-524
  text "COMPONENTS MARKED 'DNP' SHOULD NOT BE POPULATED." at 6102,-318 h30
  text ".VariantName" at 5358,-434 h30
  text "ASSEMBLY VARIANT:" at 6097,-434 h30
  text ".VersionControl_RevNumber" at 1035.5,-656.17 h30
  text "SVN REV:" at 1541.5,-656.17 h30
  text ".PCB_Rev" at 2088,-656.17 h30
  text "REV:" at 2379.5,-656.17 h30
  text ".PRJ_Number" at 3224,-656.17 h30
  text "BOARD #:" at 3769.5,-656.17 h30
  text "PCB VIEWED FROM BOTTOM SIDE" at 6246,-656.17 h30
  text ".TID" at 3224,-859.5 h30
  text "TID #:" at 3769.5,-859.5 h30
  text "TEXAS INSTRUMENTS" at 904.5,-1064.84 h30
  text ".Print_Time" at 2169,-1064.84 h30
  text ".Print_Date" at 2898,-1064.84 h30
  text "GENERATED    :" at 3767.5,-1064.84 h30
  text ".plot_File_Name" at 5440.5,-1064.84 h30
  text "PLOT NAME =" at 6246,-1064.84 h30
M9 Title Sheet:
  drawing of 57 lines, arcs and shapes, not listed
  text "1" at 739.84,8036.5 h30
  text "2" at 3235.5,8036.5 h30
  text "3" at 5724.84,8036.5 h30
  text "4" at 8231.51,8036.5 h30
  text "5" at 10730.5,8036.5 h30
  text "6" at 13235.5,8036.5 h30
  text "A" at -416.5,6893.5 h30
  text "A" at 14383.5,6893.5 h30
  text "B" at -416.5,4513.5 h30
  text "B" at 14383.5,4513.5 h30
  text "C" at -416.5,2138.5 h30
  text "C" at 14383.5,2138.5 h30
  text "PROJECT TITLE:" at 11343.5,277.5 h30
  text ".PRJ_Title" at 11393.5,144.17 h30
  text "DESIGNED FOR:" at 11343.5,-23.5 h30
  text ".PRJ_Customer" at 11393.5,-163.5 h30
  text "D" at -416.5,-231.5 h30
  text "D" at 14383.5,-231.5 h30
  text "FILE NAME:" at 11343.5,-323.5 h30
  text ".PCB_File_Name_No_Path" at 11393.5,-443.5 h30
  text "Texas Instruments (TI) and/or its licensors do not warrant the accuracy or completeness of this specification" at 6374,-605.34 h30
  text "ENGINEER:" at 11343.5,-613.5 h30
  text "LAYOUT BY:" at 12848.5,-613.5 h30
  text "or any information contained therein. TI and/or its licensors do not warrant that this design will meet" at 6329.01,-718 h30
  text ".PRJ_Engineer" at 11393.5,-768.49 h30
  text ".PCB_Layout" at 12899,-768.49 h30
  text "the specifications, will be suitable for your application or fit for any particular purpose, or will operate in" at 6329.01,-830.67 h30
  text ".Layer_Name" at 577,-858.49 h30
  text "ALTIUM DESIGNER VERSION:" at 12848.5,-923.5 h30
  text "an implementation. TI and/or its licensors do not warrant that the design is production worthy. You should" at 6329.01,-943.33 h30
  text "completely validate and test your design implementation to confirm the system functionality for your application." at 6374,-1056 h30
  text ".print_Scale" at 11393.5,-1056.83 h30
  text ".Application_BuildNumber" at 12899,-1056.83 h30
  text "1" at 739.84,-1263.5 h30
  text "2" at 3235.5,-1263.5 h30
  text "3" at 5724.84,-1263.5 h30
  text "4" at 8231.51,-1263.5 h30
  text "5" at 10730.5,-1263.5 h30
  text "6" at 13235.5,-1263.5 h30
M10 Fab Notes:
  drawing of 173 lines, arcs and shapes, not listed
  text "DESIGN INFORMATION" at 12377.02,6201 h30
  text "MIN. TRACK WIDTH:" at 11732.46,6021 h30
  text "8" at 12828.7,6021 h30
  text "MIL" at 12983.46,6021 h30
  text "MIN. CLEARANCE:" at 11732.46,5889 h30
  text "0.2" at 12768.7,5889 h30
  text "mm" at 12983.46,5889 h30
  text "MIN. VIA PAD SIZE:" at 11732.46,5757 h30
  text "24" at 12798.71,5757 h30
  text "MIL" at 12983.46,5757 h30
  text "0.05mm (2MIL)" at 12427.46,5615.29 h30
  text "MINIMUM ANNULAR RING" at 11403.23,5611 h30
  text "EXTERNAL" at 13135.46,5611 h30
  text "PER" at 11603.23,5493 h30
  text "IPC-D-275 CLASS 2 LEVEL C" at 11823.23,5493 h30
  text "MIL, HOLES" at 13311.46,5380.71 h30
  text "+/-" at 12919,5380 h30
  text "+/-" at 13773,5380 h30
  text "REGISTRATION TOLERANCES:" at 11403.23,5375 h30
  text "METAL" at 12603,5375 h30
  text "5" at 13179.2,5375 h30
  text "3" at 14012.2,5375 h30
  text "MIL" at 14128.46,5375 h30
  text "+/-" at 13773,5262 h30
  text "HOLE SIZE TOLERANCE (UNLESS OTHERWISE SPECIFIED):" at 11403.23,5257 h30
  text "3" at 14012.2,5257 h30
  text "MIL" at 14128.46,5257 h30
  text "MATERIAL:" at 11328.46,5047.54 h30
  text "FR-4 High Tg" at 12314.9,4907.21 h30
  text "FR-408" at 11749.46,4898.64 h30
  text "OTHER" at 13237.46,4898.64 h30
  text "X" at 12160,4895 h30
  text "62 MIL (1.6mm) +/-10%" at 12069.56,4735.92 h30
  text "THICKNESS:" at 11403.23,4731.64 h30
  text "X" at 11941.4,4731.64 h30
  text "OTHER" at 13354.46,4731.64 h30
  text "TOLERANCE:" at 11403.23,4573.64 h30
  text "X" at 12242.53,4573.64 h30
  text "ANSI IPC-6012 TYPE 3 CLASS 2" at 12429.48,4573.64 h30
  text "OTHER +/-" at 12429.46,4417.64 h30
  text "BOW & TWIST:" at 11403.23,4260.64 h30
  text "X" at 12242.53,4260.64 h30
  text "ANSI IPC-6012 TYPE 3 CLASS 2" at 12429.48,4260.64 h30
  text "OTHER +/-" at 12429.46,4102.13 h30
  text "DRILLING:" at 11328.46,3963.64 h30
  text "REFERENCE:" at 11403.23,3846.64 h30
  text "X" at 12051.46,3846.64 h30
  text "AS SHOWN" at 12238.46,3846.64 h30
  text "X" at 12952.46,3846.64 h30
  text "NC_DRILL FILES" at 13089.46,3846.64 h30
  text "PTH COPPER THICKNESS:" at 11403.23,3688.64 h30
  text "X" at 12533.46,3688.64 h30
  text "20-30 um" at 12670.46,3688.64 h30
  text "OTHER" at 13387.46,3688.64 h30
  text "BOARD FINISH:" at 11328.46,3529.64 h30
  text "SILKSCREEN:" at 11483.68,3411.64 h30
  text "X" at 12432.46,3411.64 h30
  text "TOP" at 12558.46,3411.64 h30
  text "X" at 12942.46,3411.64 h30
  text "BOTTOM" at 13069.46,3411.64 h30
  text "SILKSCREEN COLOR:" at 11483.68,3244.64 h30
  text "X" at 12431.42,3244.64 h30
  text "WHITE" at 12558.46,3244.64 h30
  text "OTHER" at 13069.46,3244.64 h30
  text "X" at 12562.42,3085.44 h30
  text "GREEN" at 12689.46,3085.44 h30
  text "OTHER" at 13307.46,3085.44 h30
  text "SOLDER RESIST COLOR:" at 11483.68,3074.64 h30
  text "X" at 12562.42,2915.44 h30
  text "MATTE" at 12689.46,2915.44 h30
  text "SEMI-GLOSS" at 13307,2914.8 h30
  text "IMMERSION GOLD (ENIG)" at 12389.46,2726.92 h30
  text "ENEPIG" at 13727,2723.64 h30
  text "SURFACE FINISH:" at 11328.46,2722.64 h30
  text "X" at 12202.51,2722.64 h30
  text "IMM. TIN/SILVER OR EQUIV" at 11658,2565.64 h30
  text "OTHER" at 13089.46,2565.64 h30
  text "ARRAY/PANEL:" at 11328.46,2386.64 h30
  text "CUT AND TRIM PER M1 BOARD OUTLINE" at 12389.46,2382.35 h30
  text "N.C. ROUTE" at 12389.46,2230.64 h30
  text "X" at 13068.46,2230.64 h30
  text "V. SCORE" at 13255.46,2230.64 h30
  text "CERTIFICATION:" at 11328.46,2093.64 h30
  text "MATERIALS AND WORKMANSHIP FOR ALL PCBS" at 12053.46,2093.64 h30
  text "TO MEET OR EXCEED THE REQUIREMENTS OF:" at 12053.46,1995.64 h30
  text "X" at 11679.96,1859.13 h30
  text "ANSI IPC-A-600F CLASS ->" at 11818.96,1859.13 h30
  text "X" at 13458.02,1859.13 h30
  text "2" at 13576.96,1859.14 h30
  text "1" at 13261.96,1857.64 h30
  text "3" at 13930.96,1857.64 h30
  text "X" at 12494.02,1699.64 h30
  text "RoHS" at 12630.96,1699.64 h30
  text "OTHER" at 13275.36,1699.64 h30
  text "PER ORDER" at 13672.42,1699.64 h30
  text "ALL BOARDS MUST MEET OR EXCEED UL94-V0 REQUIREMENTS." at 11356,1534 h30
  text "PCB MUST BEAR THE UL94V-0 UL REGISTERED MATERIAL ID NUMBER" at 11356,1414 h30
  text "ADDITIONAL REQUIREMENTS:" at 11328.46,1240.64 h30
  text "MICROSECTION:" at 11403.23,1125.64 h30
  text "YES" at 12308.96,1125.64 h30
  text "REQUIRED" at 13170.46,969.49 h30
  text "BARE BOARD ELEC. TEST:" at 11403.23,966.64 h30
  text "NONE" at 12708.96,966.64 h30
  text "X" at 13043.46,966.64 h30
  text "PER ORDER" at 13762.46,966.64 h30
  text ".Layer_Name" at 577,-858.49 h30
